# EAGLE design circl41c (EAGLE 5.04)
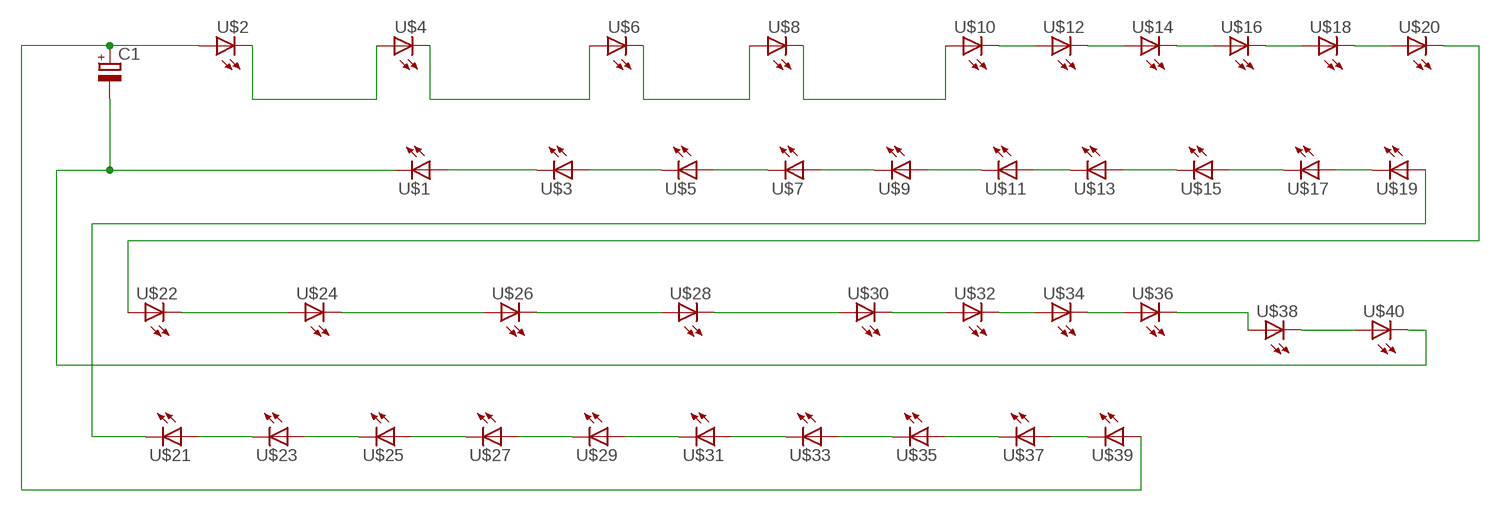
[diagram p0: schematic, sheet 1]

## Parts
C1  CPOL-EUE5-13  [E5-13]
U$1  LED5MM  [LED5MM]
U$2  LED5MM  [LED5MM]
U$3  LED5MM  [LED5MM]
U$4  LED5MM  [LED5MM]
U$5  LED5MM  [LED5MM]
U$6  LED5MM  [LED5MM]
U$7  LED5MM  [LED5MM]
U$8  LED5MM  [LED5MM]
U$9  LED5MM  [LED5MM]
U$10  LED5MM  [LED5MM]
U$11  LED5MM  [LED5MM]
U$12  LED5MM  [LED5MM]
U$13  LED5MM  [LED5MM]
U$14  LED5MM  [LED5MM]
U$15  LED5MM  [LED5MM]
U$16  LED5MM  [LED5MM]
U$17  LED5MM  [LED5MM]
U$18  LED5MM  [LED5MM]
U$19  LED5MM  [LED5MM]
U$20  LED5MM  [LED5MM]
U$21  LED5MM  [LED5MM]
U$22  LED5MM  [LED5MM]
U$23  LED5MM  [LED5MM]
U$24  LED5MM  [LED5MM]
U$25  LED5MM  [LED5MM]
U$26  LED5MM  [LED5MM]
U$27  LED5MM  [LED5MM]
U$28  LED5MM  [LED5MM]
U$29  LED5MM  [LED5MM]
U$30  LED5MM  [LED5MM]
U$31  LED5MM  [LED5MM]
U$32  LED5MM  [LED5MM]
U$33  LED5MM  [LED5MM]
U$34  LED5MM  [LED5MM]
U$35  LED5MM  [LED5MM]
U$36  LED5MM  [LED5MM]
U$37  LED5MM  [LED5MM]
U$38  LED5MM  [LED5MM]
U$39  LED5MM  [LED5MM]
U$40  LED5MM  [LED5MM]

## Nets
N$1: U$21.A U$23.K(C)
N$2: U$2.K(C) U$4.A
N$3: U$4.K(C) U$6.A
N$4: U$6.K(C) U$8.A
N$5: U$8.K(C) U$10.A
N$6: U$38.K(C) U$40.A
N$7: C1.+ U$2.A U$39.A
N$8: U$10.K(C) U$12.A
N$9: U$7.A U$9.K(C)
N$10: U$23.A U$25.K(C)
N$11: U$25.A U$27.K(C)
N$12: U$27.A U$29.K(C)
N$13: U$12.K(C) U$14.A
N$14: U$14.K(C) U$16.A
N$15: U$16.K(C) U$18.A
N$16: U$18.K(C) U$20.A
N$17: U$19.A U$21.K(C)
N$18: U$29.A U$31.K(C)
N$19: U$31.A U$33.K(C)
N$20: U$33.A U$35.K(C)
N$21: U$35.A U$37.K(C)
N$22: U$37.A U$39.K(C)
N$23: U$20.K(C) U$22.A
N$24: U$22.K(C) U$24.A
N$25: U$24.K(C) U$26.A
N$26: U$26.K(C) U$28.A
N$27: U$28.K(C) U$30.A
N$28: U$30.K(C) U$32.A
N$29: U$32.K(C) U$34.A
N$30: U$34.K(C) U$36.A
N$31: U$36.K(C) U$38.A
N$32: C1.- U$1.K(C) U$40.K(C)
N$33: U$17.A U$19.K(C)
N$34: U$15.A U$17.K(C)
N$35: U$13.A U$15.K(C)
N$36: U$11.A U$13.K(C)
N$37: U$9.A U$11.K(C)
N$38: U$5.A U$7.K(C)
N$39: U$3.A U$5.K(C)
N$40: U$1.A U$3.K(C)

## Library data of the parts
C1 = rcl-2:CPOL-EU: POLARIZED CAPACITOR, European symbol
U$1-U$40 = led(2):LED: LED

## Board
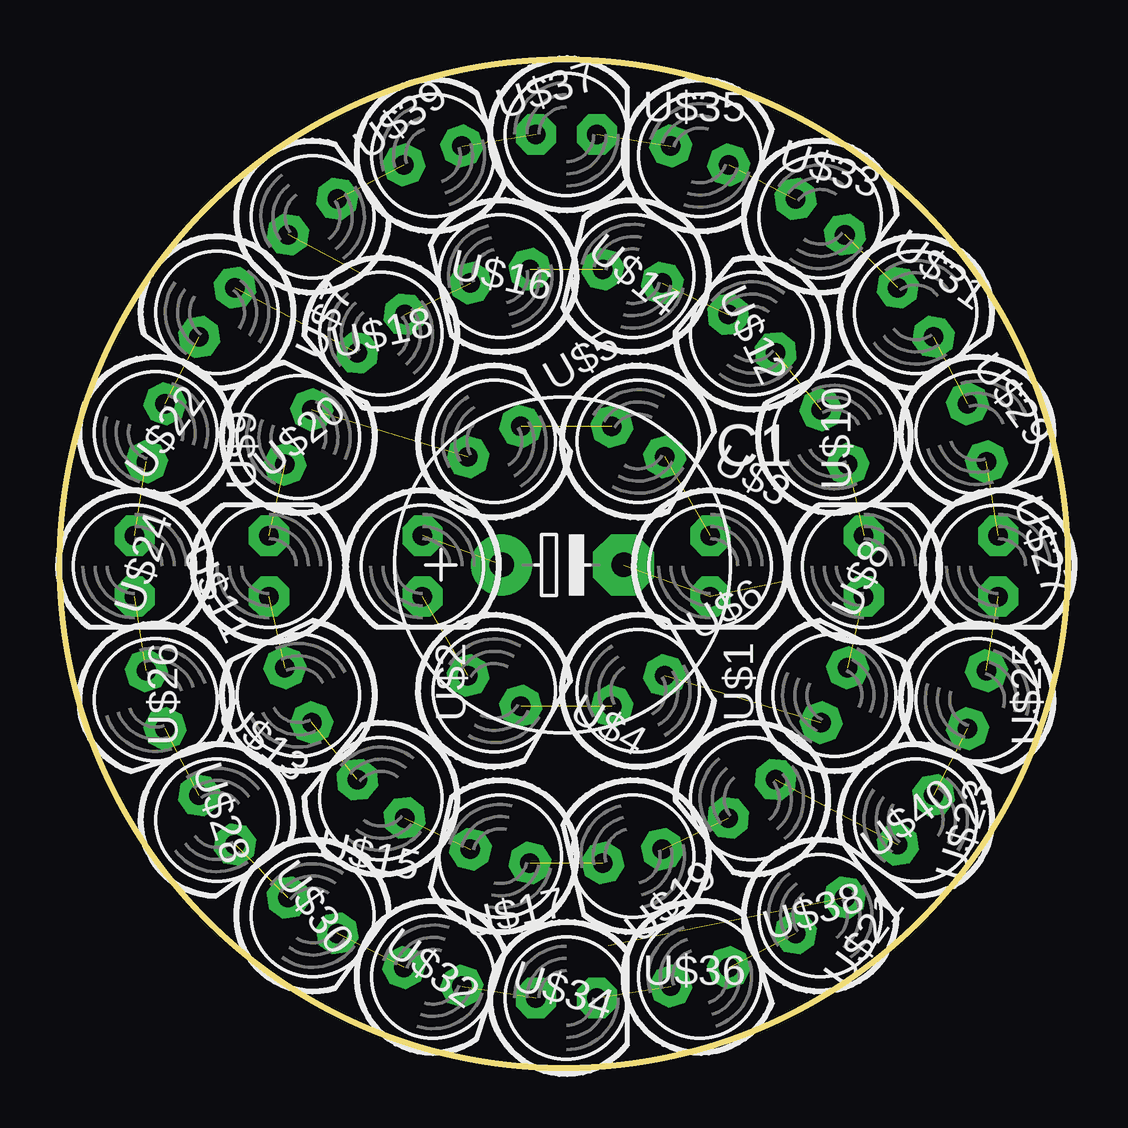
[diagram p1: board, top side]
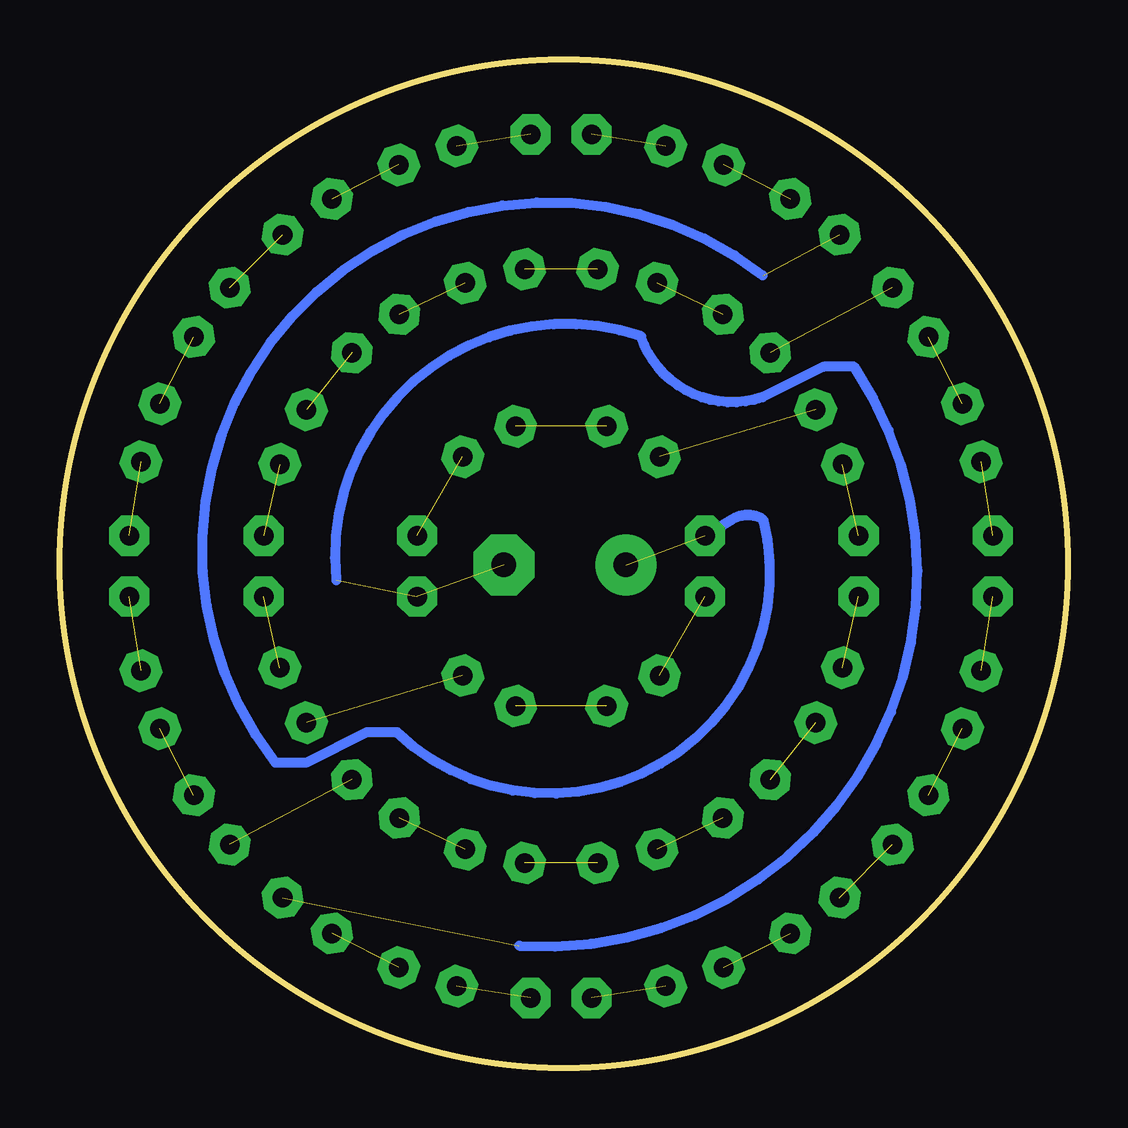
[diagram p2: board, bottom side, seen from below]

Size 42 x 42 mm. Coordinates in mm from the lower left corner, seen from the top.
Outline: circle at 21,21 radius 21
Copper layers (1*16): Top 0.035mm / dielectric 1.5mm / Bottom 0.035mm
Design rules "default": minimum track width 10mil, minimum drill 24mil, track to track 8mil, track to pad 8mil, pad to pad 8mil, via to via 8mil, smd to smd 8mil, copper to edge 40mil, drill to drill 8mil, minimum pad ring 10mil, minimum via ring 8mil, stop-mask expansion 4mil, vias tented up to drill 0mil, thermal gap 10mil

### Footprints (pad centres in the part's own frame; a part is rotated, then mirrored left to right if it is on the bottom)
E5-13 = drill 1.016 pad 2.54 round: + -2.54,0 | drill 1.016 pad 2.54 octagon: - 2.54,0
LED5MM = drill 0.813 pad 1.676 octagon: A -1.27,0; K 1.27,0

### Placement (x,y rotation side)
C1  20.95,20.95 0 top
U$1  27.11,20.9 270 top
U$2  15.11,20.9 270 top
U$3  24.11,26.1 330 top
U$4  18.11,15.7 330 top
U$5  18.11,26.1 30 top
U$6  24.11,15.7 30 top
U$7  9.94,26.28 64 top
U$8  32.28,15.52 64 top
U$9  8.71,20.9 90 top
U$10  33.51,20.9 90 top
U$11  9.94,15.52 116 top
U$12  32.28,26.28 116 top
U$13  13.38,11.21 141 top
U$14  28.84,30.59 141 top
U$15  18.35,8.81 167 top
U$16  23.87,32.99 167 top
U$17  23.87,8.81 193 top
U$18  18.35,32.99 193 top
U$19  28.84,11.21 219 top
U$20  13.38,30.59 219 top
U$21  35.67,10.32 234 top
U$22  6.55,31.48 234 top
U$23  38.23,15.34 252 top
U$24  3.99,26.46 252 top
U$25  39.11,20.9 270 top
U$26  3.11,20.9 270 top
U$27  38.23,26.46 288 top
U$28  3.99,15.34 288 top
U$29  35.67,31.48 306 top
U$30  6.55,10.32 306 top
U$31  31.69,35.46 324.1 top
U$32  10.53,6.34 324.1 top
U$33  26.67,38.02 342 top
U$34  15.55,3.78 342 top
U$35  21.11,38.9 0 top
U$36  21.11,2.9 0 top
U$37  15.55,38.02 17.9 top
U$38  26.67,3.78 17.9 top
U$39  10.53,35.46 35.9 top
U$40  31.69,6.34 35.9 top

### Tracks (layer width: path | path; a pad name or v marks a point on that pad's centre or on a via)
N$1  (1 unrouted)
N$2  (1 unrouted)
N$3  (1 unrouted)
N$4  (1 unrouted)
N$5  (1 unrouted)
N$6  (1 unrouted)
N$7  (2 unrouted)
  Bottom 0.406: U$2.A 13.97,22.86 arc62 12.7,22.86 arc148 27.94,13.97 29.21,13.97 31.75,12.7 33.02,12.7 arc166 12.7,33.02
N$8  (1 unrouted)
N$9  (1 unrouted)
N$10  (1 unrouted)
N$11  (1 unrouted)
N$12  (1 unrouted)
N$13  (1 unrouted)
N$14  (1 unrouted)
N$15  (1 unrouted)
N$16  (1 unrouted)
N$17  (1 unrouted)
N$18  (1 unrouted)
N$19  (1 unrouted)
N$20  (1 unrouted)
N$21  (1 unrouted)
N$22  (1 unrouted)
N$23  (1 unrouted)
N$24  (1 unrouted)
N$25  (1 unrouted)
N$26  (1 unrouted)
N$27  (1 unrouted)
N$28  (1 unrouted)
N$29  (1 unrouted)
N$30  (1 unrouted)
N$31  (1 unrouted)
N$32  (3 unrouted)
  Bottom 0.406: 22.86,5.08 arc-128 8.89,29.21 10.16,29.21 12.7,27.94 arc90 17.78,30.48 arc-115 30.48,20.32
N$33  (1 unrouted)
N$34  (1 unrouted)
N$35  (1 unrouted)
N$36  (1 unrouted)
N$37  (1 unrouted)
N$38  (1 unrouted)
N$39  (1 unrouted)
N$40  (1 unrouted)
